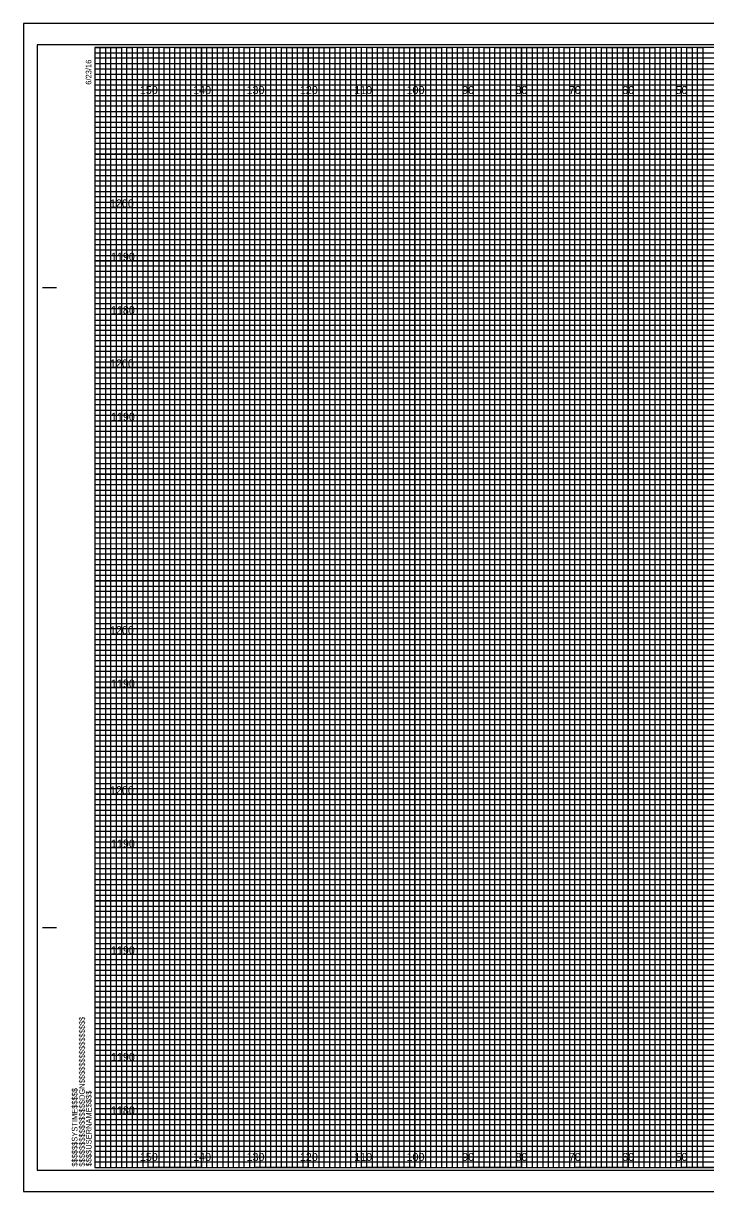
# Model space of a CAD drawing. Extents: x -13 to 323, y -5 to 215.
# Drawn here: x -13.4 to 114.5, y -4.5 to 214.5 of the extents above; entities that cross this region are included whole.
import ezdxf

# ---------------------------------------------------------------- set-up
doc = ezdxf.new("R2010")
doc.units = 0
for name, color, linetype in [('Exist XS Ground Line', 7, 'Continuous'), ('Prop CMT Pvmt Concrete', 7, 'Continuous'), ('Prop CMT Pvmt Course 2', 7, 'Continuous'), ('Prop CMT Pvmt Course 3', 7, 'Continuous'), ('Prop CMT Pvmt Course 4', 7, 'Continuous'), ('Prop CMT Pvmt Milling', 7, 'Continuous'), ('Prop CMT Shld Paved Course 1', 7, 'Continuous'), ('Prop CMT Shld Paved Course 2', 7, 'Continuous'), ('Prop CMT Shld Paved Course 4', 7, 'Continuous'), ('Prop Conc Curb and Gutter', 7, 'Continuous'), ('Prop XS Finish Grade', 7, 'Continuous')]:
    doc.layers.add(name, color=color, linetype=linetype)

msp = doc.modelspace()

# ---------------------------------------------------------------- linework, layer by layer
at = {"layer": 'Prop CMT Pvmt Course 2'}
msp.add_lwpolyline([(-10.8, -0.5), (322.4, -0.5), (322.4, 210.5), (-10.8, 210.5)], close=True, dxfattribs=at)
at = {"layer": 'Prop CMT Pvmt Course 3'}
for p, q in [((10, 0), (10, 210)), ((20, 0), (20, 210)), ((30, 0), (30, 210)), ((40, 0), (40, 210)), ((50, 0), (50, 210)), ((60, 0), (60, 210)), ((70, 0), (70, 210)), ((80, 0), (80, 210)), ((90, 0), (90, 210)), ((100, 0), (100, 210)), ((110, 0), (110, 210)), ((0, 200), (320, 200)), ((0, 190), (320, 190)), ((0, 180), (320, 180)), ((0, 170), (320, 170)), ((0, 160), (320, 160)), ((0, 150), (320, 150)), ((0, 140), (320, 140)), ((0, 130), (320, 130)), ((0, 120), (320, 120)), ((0, 110), (320, 110)), ((0, 100), (320, 100)), ((0, 90), (320, 90)), ((0, 80), (320, 80)), ((0, 70), (320, 70)), ((0, 60), (320, 60)), ((0, 50), (320, 50)), ((0, 40), (320, 40)), ((0, 30), (320, 30)), ((0, 20), (320, 20)), ((0, 10), (320, 10))]:
    msp.add_line(p, q, dxfattribs=at)
at = {"layer": 'Prop CMT Pvmt Course 4'}
msp.add_lwpolyline([(-13.4, -4.5), (323.3, -4.5), (323.3, 214.5), (-13.4, 214.5)], close=True, dxfattribs=at)
at = {"layer": 'Prop CMT Pvmt Milling'}
for points in [[(0, 0), (1, 0), (1, 210), (2, 210), (2, 0)], [(2, 0), (3, 0), (3, 210), (4, 210), (4, 0)], [(5, 0), (6, 0), (6, 210), (7, 210), (7, 0)], [(7, 0), (8, 0), (8, 210), (9, 210), (9, 0)], [(10, 0), (11, 0), (11, 210), (12, 210), (12, 0)], [(12, 0), (13, 0), (13, 210), (14, 210), (14, 0)], [(15, 0), (16, 0), (16, 210), (17, 210), (17, 0)], [(17, 0), (18, 0), (18, 210), (19, 210), (19, 0)], [(20, 0), (21, 0), (21, 210), (22, 210), (22, 0)], [(22, 0), (23, 0), (23, 210), (24, 210), (24, 0)], [(25, 0), (26, 0), (26, 210), (27, 210), (27, 0)], [(27, 0), (28, 0), (28, 210), (29, 210), (29, 0)], [(30, 0), (31, 0), (31, 210), (32, 210), (32, 0)], [(32, 0), (33, 0), (33, 210), (34, 210), (34, 0)], [(35, 0), (36, 0), (36, 210), (37, 210), (37, 0)], [(37, 0), (38, 0), (38, 210), (39, 210), (39, 0)], [(40, 0), (41, 0), (41, 210), (42, 210), (42, 0)], [(42, 0), (43, 0), (43, 210), (44, 210), (44, 0)], [(45, 0), (46, 0), (46, 210), (47, 210), (47, 0)], [(47, 0), (48, 0), (48, 210), (49, 210), (49, 0)], [(50, 0), (51, 0), (51, 210), (52, 210), (52, 0)], [(52, 0), (53, 0), (53, 210), (54, 210), (54, 0)], [(55, 0), (56, 0), (56, 210), (57, 210), (57, 0)], [(57, 0), (58, 0), (58, 210), (59, 210), (59, 0)], [(60, 0), (61, 0), (61, 210), (62, 210), (62, 0)], [(62, 0), (63, 0), (63, 210), (64, 210), (64, 0)], [(65, 0), (66, 0), (66, 210), (67, 210), (67, 0)], [(67, 0), (68, 0), (68, 210), (69, 210), (69, 0)], [(70, 0), (71, 0), (71, 210), (72, 210), (72, 0)], [(72, 0), (73, 0), (73, 210), (74, 210), (74, 0)], [(75, 0), (76, 0), (76, 210), (77, 210), (77, 0)], [(77, 0), (78, 0), (78, 210), (79, 210), (79, 0)], [(80, 0), (81, 0), (81, 210), (82, 210), (82, 0)], [(82, 0), (83, 0), (83, 210), (84, 210), (84, 0)], [(85, 0), (86, 0), (86, 210), (87, 210), (87, 0)], [(87, 0), (88, 0), (88, 210), (89, 210), (89, 0)], [(90, 0), (91, 0), (91, 210), (92, 210), (92, 0)], [(92, 0), (93, 0), (93, 210), (94, 210), (94, 0)], [(95, 0), (96, 0), (96, 210), (97, 210), (97, 0)], [(97, 0), (98, 0), (98, 210), (99, 210), (99, 0)], [(100, 0), (101, 0), (101, 210), (102, 210), (102, 0)], [(102, 0), (103, 0), (103, 210), (104, 210), (104, 0)], [(105, 0), (106, 0), (106, 210), (107, 210), (107, 0)], [(107, 0), (108, 0), (108, 210), (109, 210), (109, 0)], [(110, 0), (111, 0), (111, 210), (112, 210), (112, 0)], [(112, 0), (113, 0), (113, 210), (114, 210), (114, 0)]]:
    msp.add_lwpolyline(points, dxfattribs=at)
at = {"layer": 'Prop CMT Shld Paved Course 1'}
for p, q in [((0, 209), (260, 209)), ((260, 207.98), (0, 207.98)), ((0, 207.98), (0, 207)), ((0, 207), (260, 207)), ((260, 205.89), (0, 205.89)), ((0, 205.89), (0, 204)), ((0, 204), (320, 204))]:
    msp.add_line(p, q, dxfattribs=at)
for points in [[(0, 203), (270, 203), (320, 203), (320, 202), (0, 202)], [(0, 201), (320, 201), (320, 199), (0, 199)], [(0, 198), (320, 198), (320, 197), (0, 196.98)], [(0, 196), (320, 196), (320, 194), (0, 194)], [(0, 193), (320, 193), (320, 192), (0, 192)], [(0, 191), (320, 191), (320, 189), (0, 189)], [(0, 188), (320, 188), (320, 187), (0, 187)], [(0, 186), (320, 186), (320, 184), (0, 184)], [(0, 183), (320, 183), (320, 182), (0, 182)], [(0, 181), (320, 181), (320, 179), (0, 179)], [(0, 178), (320, 178), (320, 177), (0, 177)], [(0, 176), (320, 176), (320, 173.95), (320, 173), (320, 172), (0, 172)], [(0, 174), (320, 174), (320, 173), (0, 173)], [(0, 171), (320, 171), (320, 169), (0, 169.03)], [(0, 169.03), (320, 169), (320, 168), (0, 168)], [(0, 167), (320, 167), (320, 166), (0, 166)], [(0, 164), (320, 164), (320, 163), (0, 163)], [(0, 162), (320, 162), (320, 161), (0, 161)], [(-0.07, 158.89), (320, 158.89), (320, 157.88), (-0.07, 157.88)], [(0, 157), (320, 157), (320, 156), (0, 156)], [(0, 154), (320, 154), (320, 153), (0, 153)], [(0, 152), (320, 152), (320, 151), (0, 151)], [(0, 149), (320, 149), (320, 148), (0, 148)], [(0, 147), (320, 147), (320, 146), (0, 146)], [(0, 144), (320, 144), (320, 143), (0, 143)], [(0, 142), (320, 142), (320, 141), (0, 141)], [(0, 139), (320, 139), (319.99, 137.98), (0, 138)], [(0, 137), (320, 137), (320, 136), (0, 136)], [(0, 134), (320, 134), (320, 133), (0, 133)], [(0, 132), (320, 132), (320, 131), (0, 131)], [(0, 129), (320, 129), (320, 128), (0, 128)], [(0, 127), (320, 127), (320, 126), (0, 126)], [(0, 124), (320, 124), (320, 123), (0, 123)], [(0, 122), (320, 122), (320, 121), (0, 121)], [(0, 119), (320, 119), (320, 118), (0, 118)], [(0, 116.99), (320.07, 116.91), (320, 116), (0, 116)], [(0, 114), (320, 114), (320, 113), (0, 113)], [(0, 112), (320, 112), (320, 111), (0, 111)], [(0, 109), (320, 109), (320, 108), (0, 108)], [(0, 107), (320, 107), (320, 106), (0, 106)], [(0, 104), (320, 104), (320, 103), (0, 103)], [(0, 102), (320, 102), (320, 101), (0, 101)], [(0, 99), (320, 99), (320, 98), (0, 98)], [(0, 97), (320, 97), (320, 96), (0, 96)], [(0, 94), (320, 94), (320, 93), (0, 93)], [(0, 92), (320, 92), (320, 91), (0, 91)], [(0, 89), (320, 89), (320, 88), (0, 88)], [(0, 87), (320, 87), (320, 86), (0, 86)], [(0, 84), (320, 84), (320, 83), (0, 83)], [(0, 82), (320, 82), (320, 81), (0, 81)], [(0, 79), (320, 79), (319.99, 77.98), (0, 78)], [(0, 77), (320, 77), (320, 76), (0, 76)], [(0, 74), (320, 74), (320, 73), (0, 73)], [(0, 72), (320, 72), (320, 71), (0, 71)], [(0, 69), (320, 69), (320, 68), (0, 68)], [(0, 67), (320, 67), (320, 66), (0, 66)], [(0, 64), (320, 64), (320, 63), (0, 63)], [(0, 62), (320, 62), (320, 61), (0, 61)], [(0, 59), (320, 59), (320, 58), (0, 58)], [(0, 56.99), (320.07, 56.91), (320, 56), (0, 56)], [(0, 54), (320, 54), (320, 53), (0, 53)], [(0, 52), (320, 52), (320, 51), (0, 51)], [(0, 49), (320, 49), (320, 48), (0, 48)], [(0, 47), (320, 47), (320, 46), (0, 46)], [(0, 44), (320, 44), (320, 43), (0, 43)], [(0, 42), (320, 42), (320, 41), (0, 41)], [(0, 39), (320, 39), (320, 38), (0, 38)], [(0, 37), (320, 37), (320, 36), (0, 36)], [(0, 34), (320, 34), (320, 33), (0, 33)], [(0, 32), (320, 32), (320, 31), (0, 31)], [(0, 29), (320, 29), (320, 28), (0, 28)], [(0, 27), (320, 27), (320, 26), (0, 26)], [(0, 24), (320, 24), (320, 23), (0, 23)], [(0, 22), (320, 22), (320, 21), (0, 21)], [(0, 19), (320, 19), (320, 18), (0, 18)], [(0, 17), (320, 17), (320, 16), (0, 16)], [(0, 14), (320, 14), (320, 13), (0, 13)], [(0, 12), (320, 12), (320, 11), (0, 11)], [(0, 9), (320, 9), (320, 8), (0, 8)], [(0, 7), (320, 7), (320, 6), (0, 6)], [(0, 4), (320, 4), (320, 3), (0, 3)], [(0, 2), (320, 2), (320, 1), (0, 1)]]:
    msp.add_lwpolyline(points, dxfattribs=at)
at = {"layer": 'Prop CMT Shld Paved Course 2'}
for p, q in [((10, 210), (0, 210)), ((10, 0), (10, 210)), ((30, 210), (20, 210)), ((20, 210), (20, 0)), ((30, 0), (30, 210)), ((50, 210), (40, 210)), ((40, 210), (40, 0)), ((50, 0), (50, 210)), ((70, 210), (60, 210)), ((60, 210), (60, 0)), ((70, 0), (70, 210)), ((90, 210), (80, 210)), ((80, 210), (80, 0)), ((90, 0), (90, 210)), ((110, 210), (100, 210)), ((100, 210), (100, 0)), ((110, 0), (110, 210)), ((20, 0), (10, 0)), ((40, 0), (30, 0)), ((60, 0), (50, 0)), ((80, 0), (70, 0)), ((100, 0), (90, 0)), ((120, 0), (110, 0))]:
    msp.add_line(p, q, dxfattribs=at)
for points in [[(0, 200), (320, 200), (320, 190), (0, 190)], [(0, 180), (320, 180), (320, 170), (0, 170)], [(0, 160), (320, 160), (320, 150), (0, 150)], [(0, 140), (320, 140), (320, 130), (0, 130)], [(0, 120), (320, 120), (320, 110), (0, 110)], [(0, 100), (320, 100), (320, 90), (0, 90)], [(0, 80), (320, 80), (320, 70), (0, 70)], [(0, 60), (320, 60), (320, 50), (0, 50)], [(0, 40), (320, 40), (320, 30), (0, 30)], [(0, 20), (320, 20), (320, 10), (0, 10)]]:
    msp.add_lwpolyline(points, dxfattribs=at)
at = {"layer": 'Prop CMT Shld Paved Course 4'}
for p, q in [((-9.8, 165), (-7.3, 165)), ((-9.7, 165), (-7.2, 165)), ((-9.8, 45), (-7.3, 45)), ((-9.7, 45), (-7.2, 45)), ((0, 0), (0, 0)), ((0, 0), (0, 0)), ((0, 0), (0, 0)), ((0, 0), (0, 0)), ((0, 0), (0, 0)), ((0, 0), (0, 0)), ((0, 0), (0, 0))]:
    msp.add_line(p, q, dxfattribs=at)
msp.add_lwpolyline([(320, 210), (0, 210), (0, 0), (320, 0)], close=True, dxfattribs=at)
at = {"layer": 'Prop Conc Curb and Gutter'}
for p, q in [((323.3, 214.5), (-13.4, 214.5)), ((-13.4, 214.5), (-13.4, -4.5)), ((-13.4, -4.5), (323.3, -4.5))]:
    msp.add_line(p, q, dxfattribs=at)
at = {"layer": 'Prop XS Finish Grade'}
for points in [[(0, 210), (5, 210), (5, 0), (15, 0), (15, 210), (25, 210), (25, 0), (35, 0), (35, 210), (45, 210), (45, 0), (55, 0), (55, 210), (65, 210), (65, 0), (75, 0), (75, 210), (85, 210), (85, 0), (95, 0), (95, 210), (105, 210), (105, 0), (115, 0)], [(0, 205), (275, 205)], [(0, 185), (320, 185), (320, 195), (0, 195)], [(0, 165), (320, 165), (320, 175), (0, 175)], [(0, 145), (320, 145), (320, 155), (0, 155)], [(0, 125), (320, 125), (320, 135), (0, 135)], [(0, 105), (320, 105), (320, 115), (0, 115)], [(0, 85), (320, 85), (320, 95), (0, 95)], [(0, 65), (320, 65), (320, 75), (0, 75)], [(0, 45), (320, 45), (320, 55), (0, 55)], [(0, 25), (320, 25), (320, 35), (0, 35)], [(0, 5), (320, 5), (320, 15), (0, 15)]]:
    msp.add_lwpolyline(points, dxfattribs=at)

# ---------------------------------------------------------------- texts
at = {"layer": 'Exist XS Ground Line'}
for s, p in [('150', (8.44, 201.25)), ('140', (18.44, 201.25)), ('130', (28.44, 201.25)), ('120', (38.44, 201.25)), ('110', (48.62, 201.25)), ('100', (58.44, 201.25)), ('90', (68.86, 201.25)), ('80', (78.86, 201.25)), ('70', (88.86, 201.25)), ('60', (98.86, 201.25)), ('50', (108.86, 201.25)), ('150', (8.44, 1.25)), ('140', (18.44, 1.25)), ('130', (28.44, 1.25)), ('120', (38.44, 1.25)), ('110', (48.62, 1.25)), ('100', (58.44, 1.25)), ('90', (68.86, 1.25)), ('80', (78.86, 1.25)), ('70', (88.86, 1.25)), ('60', (98.86, 1.25)), ('50', (108.86, 1.25))]:
    msp.add_text(s, height=1.5, dxfattribs=at).set_placement(p)
at = {"layer": 'Prop CMT Pvmt Concrete'}
for s, p in [('1200', (2.85, 180)), ('1190', (3.03, 170)), ('1180', (3.03, 160)), ('1200', (2.85, 150)), ('1190', (3.03, 140)), ('1200', (2.85, 100)), ('1190', (3.03, 90)), ('1200', (2.85, 70)), ('1190', (3.03, 60)), ('1190', (3.03, 40)), ('1190', (3.03, 20)), ('1180', (3.03, 10))]:
    msp.add_text(s, height=1.5, dxfattribs=at).set_placement(p)
at = {"layer": 'Prop CMT Shld Paved Course 4'}
for s, p in [('6/23/16', (-0.65, 203)), ('$$$$$$$$$$$$$$$$DGN$$$$$$$$$$$$$$$$', (-1.88, 0.18)), ('$$$$$$SYSTIME$$$$$', (-3.26, 0.18)), ('$$$$USERNAME$$$$', (-0.62, 0.23))]:
    msp.add_text(s, height=1.05, rotation=90, dxfattribs=at).set_placement(p)

doc.saveas('drawing.dxf')
